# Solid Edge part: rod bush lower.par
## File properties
Author: Vicky Raina
Template: Normal.par
Last saved by: Robert a Rhodes jr
Revision: 2
Application: Solid Edge
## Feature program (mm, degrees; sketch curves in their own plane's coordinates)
sketch for "unnamed Protrusion 1" #1 plane through (0, 0, 0) normal (0, 0, 1) x-axis (1, 0, 0)
  circle centre (0, 0) radius 6
sketch for "unnamed Protrusion 1" #2 plane through (0, 0, 0) normal (0, 0, 1) x-axis (1, 0, 0)
  circle centre (0, 0) radius 7.5
extrude "unnamed Protrusion 1" add finite 24 along -normal
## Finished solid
Body 1: solid body, 4 faces, 4 edges, 0 vertices.
  Faces by surface: cylinder 2, plane 2
  Edges by curve: circle 4
Bounding box of the edges (mm): 15.000 x 15.000 x 24.000, from (-7.5, -7.5, -24) to (7.5, 7.5, 0).
Cylindrical faces by radius (mm): R6 x1, R7.5 x1
Planar faces by outward normal: +z 1, -z 1
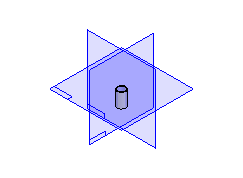
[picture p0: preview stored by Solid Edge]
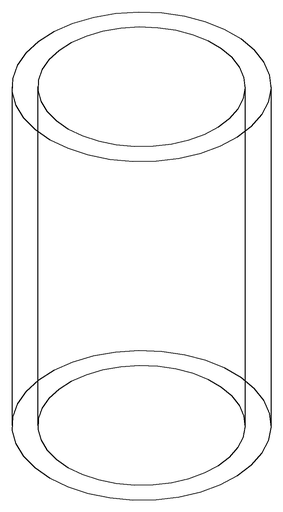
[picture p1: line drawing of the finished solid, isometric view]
